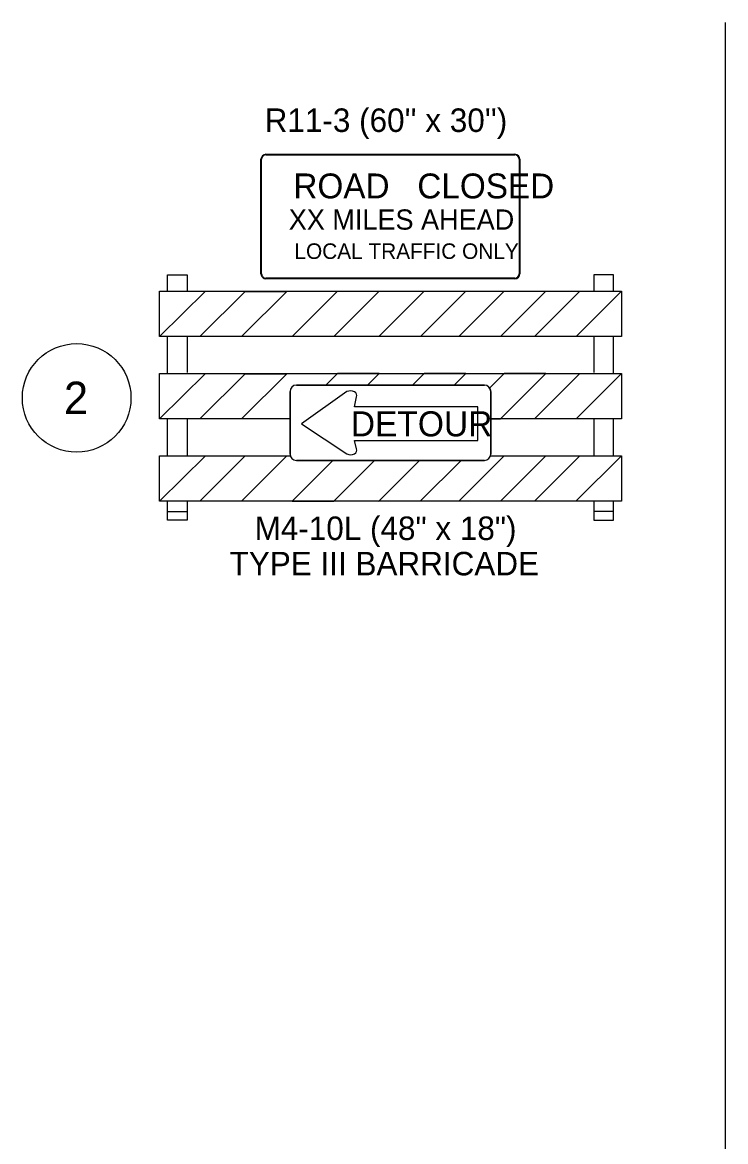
# Model space of a CAD drawing. Extents: x 886234 to 968767, y 455416 to 684046.
# Drawn here: x 926262 to 929770, y 576347 to 581931 of the extents above; entities that cross this region are included whole.
import ezdxf

# ---------------------------------------------------------------- set-up
doc = ezdxf.new("R2010")
doc.units = 0
for name, color, linetype in [('Scratch_Level_4', 7, 'Continuous'), ('TC DEV BARRICADE', 7, 'Continuous'), ('TC DEV SIGN BLACK 239', 7, 'Continuous'), ('TC DEV SIGN BLACK ZERO', 7, 'Continuous'), ('TC DEV SIGN ORANGE', 7, 'Continuous'), ('TC DEV SIGN WHITE', 7, 'Continuous'), ('TC LABEL TEXT', 7, 'Continuous')]:
    doc.layers.add(name, color=color, linetype=linetype)

msp = doc.modelspace()

# ---------------------------------------------------------------- linework, layer by layer
at = {"layer": 'Scratch_Level_4'}
msp.add_line((929770.3, 569803.5), (929770.3, 581930.6), dxfattribs=at)
at = {"layer": 'TC DEV BARRICADE'}
for p, q in [((926946.3, 580364), (926946.3, 580589.9)), ((926946.3, 580589.9), (927175.2, 580589.9)), ((927175.2, 580589.9), (926946.3, 580364)), ((927147.9, 580362.9), (927373.7, 580588.7)), ((927581, 580588.7), (927355.3, 580363)), ((927373.7, 580588.7), (927581, 580588.7)), ((927608.4, 580363.8), (927834.3, 580589.6)), ((928041.6, 580589.6), (927815.9, 580363.9)), ((927834.3, 580589.6), (928041.6, 580589.6)), ((928041.2, 580364.1), (928267.1, 580590)), ((928474.4, 580590), (928248.7, 580364.2)), ((928267.1, 580590), (928474.4, 580590)), ((928439.8, 580363.9), (928665.7, 580589.8)), ((928873, 580589.8), (928647.3, 580364.1)), ((928665.7, 580589.8), (928873, 580589.8)), ((928817.2, 580364.1), (929043, 580589.9)), ((929250.3, 580589.9), (929024.6, 580364.2)), ((929043, 580589.9), (929250.3, 580589.9)), ((927355.3, 580363), (927147.9, 580362.9)), ((927815.9, 580363.9), (927608.4, 580363.8)), ((928248.7, 580364.2), (928041.2, 580364.1)), ((928647.3, 580364.1), (928439.8, 580363.9)), ((929024.6, 580364.2), (928817.2, 580364.1)), ((926946.3, 579953.3), (926946.3, 580179.2)), ((926946.3, 580179.2), (927175.2, 580179.2)), ((927175.2, 580179.2), (926946.3, 579953.3)), ((927147.9, 579952.2), (927373.7, 580178)), ((927581, 580178), (927355.3, 579952.3)), ((927373.7, 580178), (927581, 580178)), ((927776, 580120.6), (927834.3, 580178.9)), ((927834.3, 580178.9), (927776, 580120.6)), ((927834.3, 580178.9), (928041.6, 580178.9)), ((928041.6, 580178.9), (927834.3, 580178.9)), ((928041.6, 580178.9), (927983.3, 580120.6)), ((927983.3, 580120.6), (928041.6, 580178.9)), ((928208.4, 580120.6), (928267.1, 580179.3)), ((928267, 580179.2), (928208.4, 580120.6)), ((928267.1, 580179.3), (928474.4, 580179.3)), ((928474.4, 580179.3), (928415.8, 580120.6)), ((928415.8, 580120.6), (928474.4, 580179.2)), ((928593.4, 580106.8), (928665.7, 580179.1)), ((928665.7, 580179.1), (928593.4, 580106.8)), ((928873, 580179.1), (928647.3, 579953.4)), ((928647.3, 579953.4), (928873, 580179.1)), ((928665.7, 580179.1), (928873, 580179.1)), ((928873, 580179.1), (928665.7, 580179.1)), ((928817.2, 579953.4), (929043, 580179.2)), ((929250.3, 580179.2), (929024.6, 579953.5)), ((929043, 580179.2), (929250.3, 580179.2)), ((927776, 580120.6), (927983.3, 580120.6)), ((928208.4, 580120.6), (928415.8, 580120.6)), ((928598.6, 580089.4), (928598.6, 579953.3)), ((927355.3, 579952.3), (927147.9, 579952.2)), ((928647.3, 579953.4), (928598.6, 579953.3)), ((928598.6, 579953.3), (928647.3, 579953.4)), ((929024.6, 579953.5), (928817.2, 579953.4)), ((926946.3, 579542.7), (926946.3, 579768.6)), ((926946.3, 579768.6), (927175.2, 579768.6)), ((927175.2, 579768.6), (926946.3, 579542.7)), ((927147.9, 579541.5), (927373.7, 579767.4)), ((927581, 579767.4), (927355.3, 579541.6)), ((927373.7, 579767.4), (927581, 579767.4)), ((927608.4, 579542.4), (927811.5, 579745.4)), ((927811.5, 579745.4), (927608.7, 579542.7)), ((928018.8, 579745.4), (927811.5, 579745.4)), ((928018.8, 579745.4), (927815.9, 579542.5)), ((927816, 579542.7), (928018.8, 579745.4)), ((928041.2, 579542.7), (928243.9, 579745.4)), ((928243.9, 579745.4), (928041.2, 579542.7)), ((928451.2, 579745.4), (928243.9, 579745.4)), ((928451.2, 579745.4), (928248.7, 579542.9)), ((928248.7, 579542.9), (928451.2, 579745.4)), ((928439.8, 579542.6), (928665.7, 579768.4)), ((928873, 579768.4), (928647.3, 579542.7)), ((928665.7, 579768.4), (928873, 579768.4)), ((928817.2, 579542.7), (929043, 579768.6)), ((929250.3, 579768.6), (929024.6, 579542.9)), ((929043, 579768.6), (929250.3, 579768.6)), ((926985.8, 579490.8), (927084.4, 579490.8)), ((927355.3, 579541.6), (927147.9, 579541.5)), ((927815.9, 579542.5), (927608.4, 579542.4)), ((928248.7, 579542.9), (928041.2, 579542.7)), ((928041.2, 579542.7), (928248.7, 579542.9)), ((928647.3, 579542.7), (928439.8, 579542.6)), ((929024.6, 579542.9), (928817.2, 579542.7)), ((929210.9, 579490.8), (929112.3, 579490.8))]:
    msp.add_line(p, q, dxfattribs=at)
for points in [[(926985.8, 580591.6), (926985.8, 580671.4), (927084.4, 580671.4), (927084.4, 580591.9)], [(929210.9, 580591.6), (929210.9, 580671.4), (929112.3, 580671.4), (929112.3, 580591.9)], [(928662.9, 580589.9), (929250.3, 580589.9), (929250.3, 580364), (926946.3, 580364), (926946.3, 580589.9), (927487.5, 580589.9)], [(927487.5, 580589.9), (928662.9, 580589.9)], [(926985.8, 580181.3), (926985.8, 580364.8)], [(927084.4, 580365.7), (927084.4, 580184)], [(929112.3, 580365.7), (929112.3, 580184)], [(929210.9, 580181.3), (929210.9, 580364.8)], [(927598.1, 579953.3), (926946.3, 579953.3), (926946.3, 580179.2), (927487.5, 580179.2)], [(927487.5, 580179.2), (928662.9, 580179.2)], [(928474.4, 580179.2), (928267.1, 580179.2), (928267, 580179.2)], [(928662.9, 580179.2), (929250.3, 580179.2), (929250.3, 579953.3), (928598.6, 579953.3)], [(926985.8, 579768.6), (926985.8, 579953.2)], [(927084.4, 579952.3), (927084.4, 579770.4)], [(929112.3, 579952.3), (929112.3, 579770.4)], [(929210.9, 579768.6), (929210.9, 579953.2)], [(928662.9, 579768.6), (929250.3, 579768.6), (929250.3, 579542.7), (926946.3, 579542.7), (926946.3, 579768.6), (927487.5, 579768.6)], [(927487.5, 579768.6), (927598.1, 579768.6)], [(928598.6, 579768.6), (928662.9, 579768.6)], [(927084.4, 579541.4), (927084.4, 579446.5), (926985.8, 579446.5), (926985.8, 579542.4)], [(927608.7, 579542.7), (927815.9, 579542.7), (927816, 579542.7)], [(929112.3, 579541.4), (929112.3, 579446.5), (929210.9, 579446.5), (929210.9, 579542.4)]]:
    msp.add_lwpolyline(points, dxfattribs=at)
msp.add_arc((928567.4, 580089.4), 31.3, 0, 33.7629, dxfattribs=at)
at = {"layer": 'TC DEV SIGN BLACK 239'}
msp.add_line((928719.3, 580651.6), (927477.4, 580651.6), dxfattribs=at)
for points in [[(927452.6, 580676.4), (927452.6, 581247.7)], [(927477.4, 581272.5), (928719.3, 581272.5)], [(928744.1, 581247.7), (928744.1, 580676.4)]]:
    msp.add_lwpolyline(points, dxfattribs=at)
for centre, start, end in [((927477.4, 581247.7), 90, 180), ((928719.3, 581247.7), 0, 90), ((927477.4, 580676.4), 180, 270.0009), ((928719.3, 580676.4), 270.0009, 360)]:
    msp.add_arc(centre, 24.8, start, end, dxfattribs=at)
at = {"layer": 'TC DEV SIGN BLACK ZERO'}
for p, q in [((927629.3, 580120.6), (928567.4, 580120.6)), ((927598.1, 579776.7), (927598.1, 580089.4)), ((927881.5, 580088.3), (927654.3, 579927.7)), ((927918.6, 580013), (927929.6, 580062.5)), ((928598.6, 580089.4), (928598.6, 579776.7)), ((928535.1, 580013), (927918.6, 580013)), ((928535.1, 579844.6), (928535.1, 580013)), ((927654.3, 579927.7), (927881.5, 579777.8)), ((927929.6, 579803.6), (927919.7, 579844.6)), ((927919.7, 579844.6), (928535.1, 579844.6)), ((928567.4, 579745.4), (927629.3, 579745.4))]:
    msp.add_line(p, q, dxfattribs=at)
for points in [[(928567.4, 580120.6), (927629.3, 580120.6)], [(927598.1, 580089.4), (927598.1, 579776.7)], [(928598.6, 579776.7), (928598.6, 580089.4)], [(927629.3, 579745.4), (928567.4, 579745.4)]]:
    msp.add_lwpolyline(points, dxfattribs=at)
for centre, start, end in [((927629.3, 580089.4), 90, 180), ((927629.3, 580089.4), 90, 180), ((928567.4, 580089.4), 0, 90), ((928567.4, 580089.4), 0, 90), ((927629.3, 579776.7), 180, 270), ((927629.3, 579776.7), 180, 270), ((928567.4, 579776.7), 270, 0), ((928567.4, 579776.7), 270, 0)]:
    msp.add_arc(centre, 31.3, start, end, dxfattribs=at)
for centre, start_param, end_param in [((927899.4, 580069.5), 2.830616, 5.313575), ((927899.4, 579796.6), 0.969609, 3.452568)]:
    msp.add_ellipse(centre, major_axis=(-31.7, 0), ratio=0.720018, start_param=start_param, end_param=end_param, dxfattribs=at)
at = {"layer": 'TC DEV SIGN ORANGE'}
for p, q in [((927881.5, 580088.3), (927654.3, 579927.7)), ((927918.6, 580013), (927929.6, 580062.5)), ((928535.1, 580013), (927918.6, 580013)), ((928535.1, 579844.6), (928535.1, 580013)), ((927654.3, 579927.7), (927881.5, 579777.8)), ((927929.6, 579803.6), (927919.7, 579844.6)), ((927919.7, 579844.6), (928535.1, 579844.6))]:
    msp.add_line(p, q, dxfattribs=at)
for centre, start_param, end_param in [((927899.4, 580069.5), 2.830616, 5.313575), ((927899.4, 579796.6), 0.969609, 3.452568)]:
    msp.add_ellipse(centre, major_axis=(-31.7, 0), ratio=0.720018, start_param=start_param, end_param=end_param, dxfattribs=at)
at = {"layer": 'TC DEV SIGN WHITE'}
msp.add_line((928719.3, 580654.7), (927477.4, 580654.7), dxfattribs=at)
for points in [[(927455.7, 580676.4), (927455.7, 581247.7)], [(927477.4, 581269.4), (928719.3, 581269.4)], [(928741, 581247.7), (928741, 580676.4)]]:
    msp.add_lwpolyline(points, dxfattribs=at)
for centre, start, end in [((927477.4, 581247.7), 90, 180), ((928719.3, 581247.7), 0, 90), ((927477.4, 580676.4), 180, 270.0009), ((928719.3, 580676.4), 270.0009, 360)]:
    msp.add_arc(centre, 21.7, start, end, dxfattribs=at)
at = {"layer": 'TC LABEL TEXT'}
msp.add_circle((926533.2, 580057.3), 270.9, dxfattribs=at)

# ---------------------------------------------------------------- texts
at = {"layer": 'TC DEV BARRICADE'}
for s, p in [("R11-3 (60'' x 30'')", (927471, 581383.9)), ('M4-10L (48" x 18")', (927420.8, 579348.1)), ('TYPE III BARRICADE', (927296.1, 579171.7))]:
    msp.add_text(s, height=117.351, dxfattribs=at).set_placement(p)
at = {"layer": 'TC DEV SIGN BLACK 239'}
for s, height, p in [('ROAD   CLOSED', 124.186, (927614.2, 581052.6)), ('XX MILES AHEAD', 100.901, (927591.1, 580896.6)), ('LOCAL TRAFFIC ONLY', 77.616, (927619.5, 580750.5))]:
    msp.add_text(s, height=height, rotation=360, dxfattribs=at).set_placement(p)
at = {"layer": 'TC DEV SIGN BLACK ZERO'}
msp.add_text('DETOUR', height=125.07, dxfattribs=at).set_placement((927900.6, 579865.2))
at = {"layer": 'TC LABEL TEXT'}
msp.add_text('2', height=162, dxfattribs=at).set_placement((926469.6, 579976.3))

doc.saveas('drawing.dxf')
